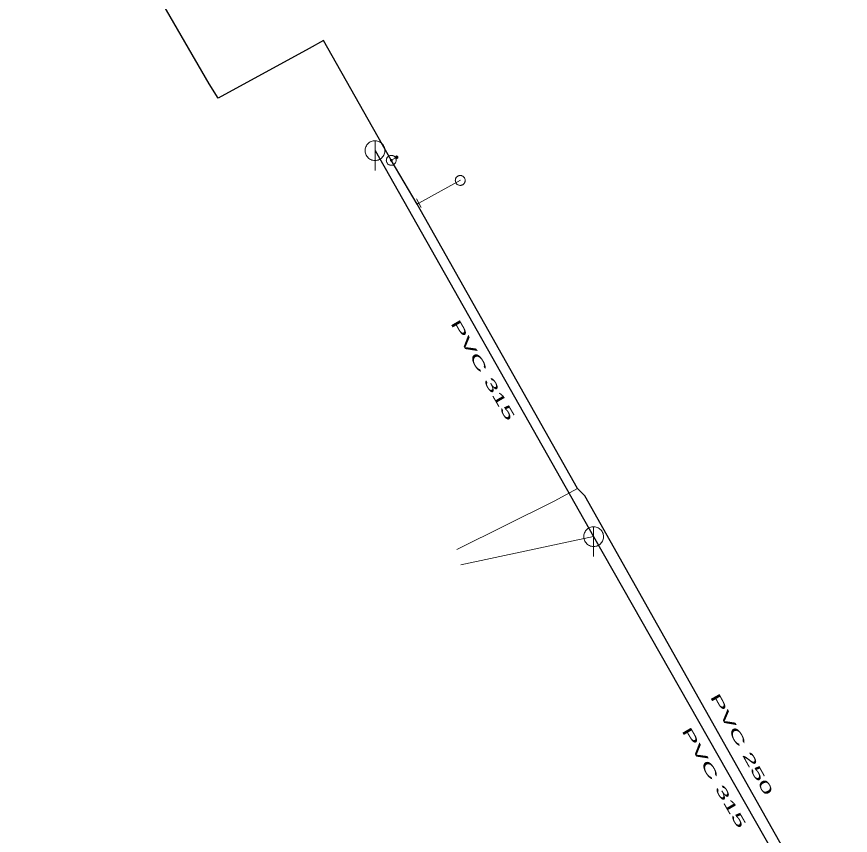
# Model space of a CAD drawing. Extents: x -807203 to -805207, y -993656 to -992505.
# Drawn here: x -806782.7 to -806698.5, y -992964 to -992881.3 of the extents above; entities that cross this region are included whole.
import ezdxf

# ---------------------------------------------------------------- set-up
doc = ezdxf.new("R2010")
doc.units = 0
doc.header["$LTSCALE"] = 0.4
for name, color, linetype, lineweight in [('1', 7, 'Continuous', 13), ('11', 7, 'Continuous', 13), ('13', 7, 'Continuous', 13), ('14', 7, 'Continuous', 25), ('17', 7, 'Continuous', 25), ('22', 7, 'Continuous', 13), ('23', 7, 'Continuous', 13), ('34', 7, 'Continuous', 13), ('47', 7, 'Continuous', 13), ('9', 7, 'Continuous', 13)]:
    doc.layers.add(name, color=color, linetype=linetype, lineweight=lineweight)

msp = doc.modelspace()

# ---------------------------------------------------------------- linework, layer by layer
at = {"layer": '11'}
msp.add_line((-806737.84, -992936.689), (-806724.449, -992933.829), dxfattribs=at)
at = {"layer": '13'}
msp.add_line((-806742.088, -992900.162), (-806737.898, -992897.848), dxfattribs=at)
msp.add_lwpolyline([(-806726.08, -992928.98), (-806728.42, -992930.24), (-806738.26, -992935.13)], dxfattribs=at)
at = {"layer": '14'}
for p, q in [((-806746.51, -992894.87), (-806724.449, -992933.829)), ((-806724.449, -992933.829), (-806699.85, -992977.12))]:
    msp.add_line(p, q, dxfattribs=at)
at = {"layer": '14', "lineweight": 13}
for p, q in [((-806744.869, -992895.849), (-806744.323, -992895.536)), ((-806742.088, -992900.162), (-806742.265, -992900.26))]:
    msp.add_line(p, q, dxfattribs=at)
at = {"layer": '17'}
for points in [[(-806744.869, -992895.849), (-806751.715, -992883.767), (-806753.16, -992884.579), (-806762.344, -992889.559), (-806763.23, -992888.129), (-806769.25, -992877.71), (-806781.199, -992856.899), (-806796.3, -992830.96), (-806805.559, -992815.579), (-806823.289, -992784.289), (-806834.87, -992763.203)], [(-806698.548, -992977.42), (-806698.73, -992976.969), (-806725.329, -992929.699), (-806726.079, -992928.98), (-806742.265, -992900.26), (-806744.869, -992895.849)]]:
    msp.add_lwpolyline(points, dxfattribs=at)
at = {"layer": '22'}
for p, q in [((-806746.51, -992896.87), (-806746.509, -992893.87)), ((-806724.449, -992935.829), (-806724.448, -992932.829))]:
    msp.add_line(p, q, dxfattribs=at)
for points in [[(-806745.51, -992894.87), (-806745.515, -992894.761), (-806745.533, -992894.653), (-806745.563, -992894.547), (-806745.603, -992894.446), (-806745.655, -992894.349), (-806745.717, -992894.259), (-806745.789, -992894.176), (-806745.869, -992894.102), (-806745.957, -992894.036), (-806746.051, -992893.981), (-806746.151, -992893.936), (-806746.256, -992893.903), (-806746.363, -992893.881), (-806746.472, -992893.871), (-806746.582, -992893.873), (-806746.69, -992893.887), (-806746.797, -992893.912), (-806746.9, -992893.949), (-806746.998, -992893.998), (-806747.09, -992894.056), (-806747.176, -992894.125), (-806747.253, -992894.202), (-806747.322, -992894.288), (-806747.381, -992894.38), (-806747.429, -992894.478), (-806747.466, -992894.581), (-806747.492, -992894.688), (-806747.506, -992894.796), (-806747.509, -992894.906), (-806747.499, -992895.015), (-806747.478, -992895.122), (-806747.444, -992895.226), (-806747.4, -992895.326), (-806747.345, -992895.421), (-806747.279, -992895.509), (-806747.205, -992895.589), (-806747.122, -992895.661), (-806747.032, -992895.723), (-806746.936, -992895.775), (-806746.834, -992895.816), (-806746.729, -992895.846), (-806746.621, -992895.864), (-806746.511, -992895.87), (-806746.402, -992895.864), (-806746.294, -992895.846), (-806746.189, -992895.817), (-806746.087, -992895.776), (-806745.99, -992895.724), (-806745.9, -992895.662), (-806745.817, -992895.591), (-806745.742, -992895.511), (-806745.677, -992895.423), (-806745.621, -992895.329), (-806745.577, -992895.229), (-806745.543, -992895.125), (-806745.521, -992895.017), (-806745.511, -992894.908)], [(-806723.449, -992933.829), (-806723.454, -992933.72), (-806723.472, -992933.612), (-806723.502, -992933.506), (-806723.542, -992933.405), (-806723.594, -992933.308), (-806723.656, -992933.218), (-806723.728, -992933.135), (-806723.808, -992933.061), (-806723.896, -992932.995), (-806723.99, -992932.94), (-806724.09, -992932.895), (-806724.195, -992932.862), (-806724.302, -992932.84), (-806724.411, -992932.83), (-806724.521, -992932.832), (-806724.629, -992932.846), (-806724.736, -992932.871), (-806724.839, -992932.908), (-806724.937, -992932.957), (-806725.029, -992933.015), (-806725.115, -992933.084), (-806725.192, -992933.161), (-806725.261, -992933.247), (-806725.32, -992933.339), (-806725.368, -992933.437), (-806725.405, -992933.54), (-806725.431, -992933.647), (-806725.445, -992933.755), (-806725.448, -992933.865), (-806725.438, -992933.974), (-806725.417, -992934.081), (-806725.383, -992934.185), (-806725.339, -992934.285), (-806725.284, -992934.38), (-806725.218, -992934.468), (-806725.144, -992934.548), (-806725.061, -992934.62), (-806724.971, -992934.682), (-806724.875, -992934.734), (-806724.773, -992934.775), (-806724.668, -992934.805), (-806724.56, -992934.823), (-806724.45, -992934.829), (-806724.341, -992934.823), (-806724.233, -992934.805), (-806724.128, -992934.776), (-806724.026, -992934.735), (-806723.929, -992934.683), (-806723.839, -992934.621), (-806723.756, -992934.55), (-806723.681, -992934.47), (-806723.616, -992934.382), (-806723.56, -992934.288), (-806723.516, -992934.188), (-806723.482, -992934.084), (-806723.46, -992933.976), (-806723.45, -992933.867)]]:
    msp.add_lwpolyline(points, close=True, dxfattribs=at)
at = {"layer": '23'}
for points in [[(-806737.471, -992897.632), (-806737.5, -992897.587), (-806737.533, -992897.546), (-806737.57, -992897.51), (-806737.61, -992897.477), (-806737.653, -992897.448), (-806737.701, -992897.424), (-806737.749, -992897.405), (-806737.799, -992897.391), (-806737.851, -992897.382), (-806737.903, -992897.379), (-806737.955, -992897.381), (-806738.008, -992897.389), (-806738.058, -992897.402), (-806738.106, -992897.421), (-806738.153, -992897.443), (-806738.198, -992897.473), (-806738.238, -992897.504), (-806738.276, -992897.542), (-806738.309, -992897.581), (-806738.338, -992897.624), (-806738.362, -992897.673), (-806738.381, -992897.721), (-806738.395, -992897.772), (-806738.404, -992897.823), (-806738.407, -992897.875), (-806738.404, -992897.928), (-806738.396, -992897.978), (-806738.383, -992898.029), (-806738.364, -992898.078), (-806738.342, -992898.125), (-806738.314, -992898.169), (-806738.281, -992898.211), (-806738.244, -992898.248), (-806738.204, -992898.281), (-806738.16, -992898.309), (-806738.114, -992898.333), (-806738.065, -992898.353), (-806738.014, -992898.367), (-806737.962, -992898.375)], [(-806738.276, -992897.542), (-806738.309, -992897.581), (-806738.338, -992897.624), (-806738.362, -992897.673), (-806738.381, -992897.721), (-806738.395, -992897.772), (-806738.404, -992897.823), (-806738.407, -992897.875), (-806738.404, -992897.928), (-806738.396, -992897.978), (-806738.383, -992898.029), (-806738.364, -992898.078), (-806738.342, -992898.125), (-806738.314, -992898.169), (-806738.281, -992898.211), (-806738.244, -992898.248), (-806738.204, -992898.281), (-806738.16, -992898.309), (-806738.114, -992898.333), (-806738.065, -992898.353), (-806738.014, -992898.367), (-806737.962, -992898.375), (-806737.911, -992898.379), (-806737.858, -992898.376), (-806737.807, -992898.369), (-806737.756, -992898.355), (-806737.708, -992898.336), (-806737.661, -992898.314), (-806737.617, -992898.285), (-806737.575, -992898.253), (-806737.538, -992898.216), (-806737.505, -992898.175), (-806737.476, -992898.131), (-806737.452, -992898.086), (-806737.433, -992898.036), (-806737.418, -992897.987), (-806737.41, -992897.935), (-806737.407, -992897.882), (-806737.409, -992897.83), (-806737.417, -992897.778)], [(-806737.962, -992898.375), (-806737.911, -992898.379), (-806737.858, -992898.376), (-806737.807, -992898.369), (-806737.756, -992898.355), (-806737.708, -992898.336), (-806737.661, -992898.314), (-806737.617, -992898.285), (-806737.575, -992898.253), (-806737.538, -992898.216), (-806737.505, -992898.175), (-806737.476, -992898.131), (-806737.452, -992898.086), (-806737.433, -992898.036), (-806737.418, -992897.987), (-806737.41, -992897.935), (-806737.407, -992897.882), (-806737.409, -992897.83), (-806737.417, -992897.778), (-806737.431, -992897.728), (-806737.449, -992897.679), (-806737.471, -992897.632), (-806737.5, -992897.587), (-806737.533, -992897.546), (-806737.57, -992897.51), (-806737.61, -992897.477), (-806737.653, -992897.448), (-806737.701, -992897.424), (-806737.749, -992897.405), (-806737.799, -992897.391), (-806737.851, -992897.382), (-806737.903, -992897.379), (-806737.955, -992897.381), (-806738.008, -992897.389), (-806738.058, -992897.402), (-806738.106, -992897.421), (-806738.153, -992897.443), (-806738.198, -992897.473), (-806738.238, -992897.504), (-806738.276, -992897.542)], [(-806737.417, -992897.778), (-806737.431, -992897.728), (-806737.449, -992897.679), (-806737.471, -992897.632)]]:
    msp.add_lwpolyline(points, dxfattribs=at)
at = {"layer": '34'}
msp.add_line((-806742.33, -992899.724), (-806741.846, -992900.599), dxfattribs=at)
at = {"layer": '47'}
for points in [[(-806744.614, -992896.279), (-806744.571, -992896.25), (-806744.53, -992896.217), (-806744.494, -992896.179), (-806744.461, -992896.139), (-806744.433, -992896.094), (-806744.41, -992896.047), (-806744.392, -992895.998), (-806744.379, -992895.947), (-806744.371, -992895.896), (-806744.369, -992895.844), (-806744.372, -992895.791), (-806744.381, -992895.74), (-806744.395, -992895.689), (-806744.414, -992895.641), (-806744.438, -992895.594), (-806744.467, -992895.551), (-806744.5, -992895.51), (-806744.538, -992895.473), (-806744.578, -992895.441), (-806744.623, -992895.413), (-806744.67, -992895.39), (-806744.719, -992895.371), (-806744.77, -992895.358), (-806744.821, -992895.35), (-806744.873, -992895.349), (-806744.926, -992895.352), (-806744.978, -992895.36), (-806745.028, -992895.375), (-806745.076, -992895.394), (-806745.123, -992895.418), (-806745.166, -992895.447), (-806745.207, -992895.48), (-806745.244, -992895.517), (-806745.276, -992895.558), (-806745.304, -992895.603), (-806745.328, -992895.649), (-806745.346, -992895.699), (-806745.359, -992895.749), (-806745.367, -992895.801), (-806745.368, -992895.853), (-806745.365, -992895.906), (-806745.357, -992895.957), (-806745.342, -992896.008), (-806745.323, -992896.056), (-806745.299, -992896.103), (-806745.27, -992896.146), (-806745.237, -992896.187), (-806745.2, -992896.223), (-806745.159, -992896.256), (-806745.114, -992896.284), (-806745.068, -992896.308), (-806745.019, -992896.325), (-806744.968, -992896.338), (-806744.916, -992896.346), (-806744.864, -992896.348), (-806744.811, -992896.345), (-806744.76, -992896.336), (-806744.709, -992896.322), (-806744.661, -992896.303)], [(-806744.827, -992895.919), (-806744.819, -992895.915), (-806744.813, -992895.909), (-806744.807, -992895.903), (-806744.802, -992895.896), (-806744.797, -992895.889), (-806744.794, -992895.881), (-806744.79, -992895.873), (-806744.788, -992895.865), (-806744.787, -992895.856), (-806744.787, -992895.848), (-806744.787, -992895.839), (-806744.789, -992895.83), (-806744.791, -992895.822), (-806744.793, -992895.815), (-806744.798, -992895.807), (-806744.802, -992895.799), (-806744.808, -992895.793), (-806744.814, -992895.787), (-806744.821, -992895.782), (-806744.828, -992895.777), (-806744.836, -992895.774), (-806744.844, -992895.77), (-806744.852, -992895.768), (-806744.861, -992895.766), (-806744.869, -992895.767), (-806744.878, -992895.767), (-806744.887, -992895.769), (-806744.895, -992895.771), (-806744.902, -992895.773), (-806744.91, -992895.778), (-806744.918, -992895.782), (-806744.924, -992895.788), (-806744.93, -992895.794), (-806744.935, -992895.801), (-806744.94, -992895.808), (-806744.944, -992895.815), (-806744.947, -992895.824), (-806744.949, -992895.832), (-806744.951, -992895.841), (-806744.95, -992895.849), (-806744.95, -992895.858), (-806744.948, -992895.867), (-806744.946, -992895.875), (-806744.944, -992895.882), (-806744.939, -992895.89), (-806744.935, -992895.898), (-806744.929, -992895.904), (-806744.923, -992895.91), (-806744.916, -992895.915), (-806744.909, -992895.92), (-806744.902, -992895.924), (-806744.893, -992895.927), (-806744.885, -992895.929), (-806744.876, -992895.93), (-806744.868, -992895.93), (-806744.859, -992895.93), (-806744.85, -992895.928), (-806744.842, -992895.926), (-806744.835, -992895.924)]]:
    msp.add_lwpolyline(points, close=True, dxfattribs=at)
at = {"layer": '9'}
for points in [[(-806744.449, -992895.536), (-806744.449, -992895.549), (-806744.446, -992895.562), (-806744.444, -992895.575), (-806744.439, -992895.587), (-806744.433, -992895.599), (-806744.426, -992895.61), (-806744.418, -992895.62), (-806744.407, -992895.63), (-806744.397, -992895.638), (-806744.387, -992895.645), (-806744.375, -992895.651), (-806744.363, -992895.656), (-806744.35, -992895.659), (-806744.337, -992895.661), (-806744.324, -992895.663), (-806744.311, -992895.662), (-806744.298, -992895.66), (-806744.285, -992895.657), (-806744.272, -992895.652), (-806744.261, -992895.646), (-806744.25, -992895.639), (-806744.24, -992895.631), (-806744.23, -992895.621), (-806744.222, -992895.611), (-806744.215, -992895.6), (-806744.209, -992895.588), (-806744.204, -992895.576), (-806744.201, -992895.563), (-806744.199, -992895.55), (-806744.196, -992895.537), (-806744.198, -992895.524), (-806744.2, -992895.511), (-806744.203, -992895.498), (-806744.208, -992895.486), (-806744.213, -992895.474), (-806744.221, -992895.463), (-806744.228, -992895.453), (-806744.239, -992895.443), (-806744.249, -992895.435), (-806744.26, -992895.428), (-806744.272, -992895.422), (-806744.284, -992895.417), (-806744.297, -992895.414), (-806744.309, -992895.412), (-806744.323, -992895.411), (-806744.336, -992895.411), (-806744.348, -992895.413), (-806744.362, -992895.416), (-806744.374, -992895.421), (-806744.386, -992895.427), (-806744.397, -992895.434), (-806744.407, -992895.442), (-806744.417, -992895.452), (-806744.424, -992895.462), (-806744.432, -992895.473), (-806744.438, -992895.485), (-806744.443, -992895.497), (-806744.446, -992895.51), (-806744.448, -992895.523)], [(-806744.429, -992895.536), (-806744.429, -992895.547), (-806744.428, -992895.558), (-806744.424, -992895.569), (-806744.421, -992895.579), (-806744.416, -992895.589), (-806744.41, -992895.598), (-806744.402, -992895.607), (-806744.395, -992895.615), (-806744.386, -992895.622), (-806744.377, -992895.628), (-806744.367, -992895.633), (-806744.357, -992895.637), (-806744.346, -992895.64), (-806744.335, -992895.643), (-806744.324, -992895.643), (-806744.313, -992895.643), (-806744.302, -992895.641), (-806744.291, -992895.638), (-806744.281, -992895.634), (-806744.271, -992895.629), (-806744.262, -992895.623), (-806744.253, -992895.616), (-806744.245, -992895.608), (-806744.238, -992895.599), (-806744.232, -992895.59), (-806744.227, -992895.58), (-806744.223, -992895.57), (-806744.22, -992895.559), (-806744.218, -992895.548), (-806744.217, -992895.537), (-806744.217, -992895.526), (-806744.218, -992895.515), (-806744.222, -992895.504), (-806744.226, -992895.494), (-806744.231, -992895.484), (-806744.237, -992895.475), (-806744.244, -992895.466), (-806744.252, -992895.458), (-806744.261, -992895.451), (-806744.27, -992895.445), (-806744.28, -992895.44), (-806744.289, -992895.436), (-806744.301, -992895.433), (-806744.311, -992895.431), (-806744.323, -992895.431), (-806744.334, -992895.43), (-806744.345, -992895.432), (-806744.356, -992895.435), (-806744.365, -992895.439), (-806744.375, -992895.444), (-806744.385, -992895.45), (-806744.394, -992895.457), (-806744.402, -992895.465), (-806744.409, -992895.474), (-806744.414, -992895.483), (-806744.419, -992895.493), (-806744.424, -992895.503), (-806744.427, -992895.514), (-806744.429, -992895.525)], [(-806744.41, -992895.536), (-806744.41, -992895.545), (-806744.409, -992895.554), (-806744.406, -992895.563), (-806744.402, -992895.571), (-806744.399, -992895.579), (-806744.394, -992895.587), (-806744.387, -992895.594), (-806744.382, -992895.6), (-806744.375, -992895.606), (-806744.367, -992895.611), (-806744.358, -992895.615), (-806744.351, -992895.618), (-806744.342, -992895.621), (-806744.333, -992895.622), (-806744.324, -992895.624), (-806744.315, -992895.623), (-806744.306, -992895.622), (-806744.297, -992895.619), (-806744.289, -992895.616), (-806744.281, -992895.612), (-806744.272, -992895.607), (-806744.266, -992895.601), (-806744.26, -992895.595), (-806744.254, -992895.588), (-806744.249, -992895.58), (-806744.245, -992895.572), (-806744.242, -992895.564), (-806744.239, -992895.555), (-806744.238, -992895.546), (-806744.235, -992895.537), (-806744.237, -992895.528), (-806744.238, -992895.519), (-806744.24, -992895.51), (-806744.244, -992895.502), (-806744.248, -992895.494), (-806744.253, -992895.486), (-806744.259, -992895.479), (-806744.265, -992895.473), (-806744.272, -992895.467), (-806744.28, -992895.462), (-806744.288, -992895.458), (-806744.296, -992895.455), (-806744.304, -992895.452), (-806744.314, -992895.451), (-806744.323, -992895.45), (-806744.331, -992895.45), (-806744.341, -992895.451), (-806744.35, -992895.454), (-806744.358, -992895.457), (-806744.365, -992895.461), (-806744.374, -992895.466), (-806744.38, -992895.472), (-806744.387, -992895.478), (-806744.392, -992895.485), (-806744.397, -992895.493), (-806744.402, -992895.501), (-806744.405, -992895.509), (-806744.407, -992895.518), (-806744.409, -992895.527)], [(-806744.39, -992895.536), (-806744.39, -992895.543), (-806744.389, -992895.55), (-806744.387, -992895.557), (-806744.385, -992895.563), (-806744.382, -992895.569), (-806744.378, -992895.575), (-806744.374, -992895.581), (-806744.369, -992895.586), (-806744.363, -992895.59), (-806744.357, -992895.594), (-806744.351, -992895.597), (-806744.345, -992895.6), (-806744.338, -992895.601), (-806744.331, -992895.604), (-806744.324, -992895.604), (-806744.316, -992895.604), (-806744.309, -992895.602), (-806744.303, -992895.601), (-806744.297, -992895.598), (-806744.289, -992895.595), (-806744.285, -992895.591), (-806744.279, -992895.587), (-806744.274, -992895.582), (-806744.27, -992895.576), (-806744.266, -992895.57), (-806744.262, -992895.564), (-806744.26, -992895.558), (-806744.258, -992895.551), (-806744.257, -992895.544), (-806744.255, -992895.537), (-806744.255, -992895.53), (-806744.257, -992895.523), (-806744.259, -992895.516), (-806744.262, -992895.51), (-806744.265, -992895.503), (-806744.269, -992895.498), (-806744.272, -992895.492), (-806744.277, -992895.487), (-806744.284, -992895.483), (-806744.289, -992895.479), (-806744.296, -992895.476), (-806744.302, -992895.473), (-806744.309, -992895.471), (-806744.316, -992895.47), (-806744.323, -992895.47), (-806744.33, -992895.47), (-806744.337, -992895.47), (-806744.343, -992895.472), (-806744.35, -992895.475), (-806744.356, -992895.478), (-806744.362, -992895.482), (-806744.368, -992895.486), (-806744.373, -992895.491), (-806744.377, -992895.497), (-806744.38, -992895.502), (-806744.384, -992895.509), (-806744.387, -992895.515), (-806744.387, -992895.522), (-806744.39, -992895.529)], [(-806744.37, -992895.536), (-806744.37, -992895.541), (-806744.37, -992895.546), (-806744.369, -992895.551), (-806744.367, -992895.555), (-806744.365, -992895.56), (-806744.362, -992895.564), (-806744.358, -992895.567), (-806744.355, -992895.571), (-806744.352, -992895.574), (-806744.348, -992895.577), (-806744.343, -992895.579), (-806744.338, -992895.581), (-806744.334, -992895.582), (-806744.329, -992895.584), (-806744.324, -992895.584), (-806744.319, -992895.584), (-806744.314, -992895.583), (-806744.309, -992895.582), (-806744.304, -992895.58), (-806744.299, -992895.578), (-806744.296, -992895.575), (-806744.292, -992895.572), (-806744.289, -992895.568), (-806744.286, -992895.565), (-806744.282, -992895.561), (-806744.281, -992895.556), (-806744.279, -992895.552), (-806744.277, -992895.547), (-806744.277, -992895.542), (-806744.276, -992895.537), (-806744.276, -992895.532), (-806744.277, -992895.527), (-806744.277, -992895.522), (-806744.28, -992895.518), (-806744.282, -992895.513), (-806744.285, -992895.509), (-806744.288, -992895.505), (-806744.291, -992895.502), (-806744.294, -992895.499), (-806744.299, -992895.496), (-806744.304, -992895.494), (-806744.308, -992895.492), (-806744.313, -992895.491), (-806744.318, -992895.49), (-806744.323, -992895.49), (-806744.328, -992895.49), (-806744.333, -992895.491), (-806744.338, -992895.491), (-806744.342, -992895.493), (-806744.347, -992895.495), (-806744.351, -992895.498), (-806744.353, -992895.501), (-806744.358, -992895.504), (-806744.36, -992895.508), (-806744.364, -992895.512), (-806744.365, -992895.517), (-806744.368, -992895.521), (-806744.369, -992895.526), (-806744.37, -992895.531)], [(-806744.35, -992895.536), (-806744.35, -992895.539), (-806744.351, -992895.542), (-806744.35, -992895.544), (-806744.348, -992895.547), (-806744.348, -992895.55), (-806744.346, -992895.552), (-806744.343, -992895.554), (-806744.342, -992895.556), (-806744.34, -992895.558), (-806744.338, -992895.56), (-806744.335, -992895.562), (-806744.331, -992895.563), (-806744.33, -992895.563), (-806744.326, -992895.564), (-806744.324, -992895.564), (-806744.321, -992895.564), (-806744.318, -992895.564), (-806744.315, -992895.563), (-806744.313, -992895.562), (-806744.309, -992895.561), (-806744.308, -992895.559), (-806744.304, -992895.557), (-806744.303, -992895.555), (-806744.302, -992895.553), (-806744.299, -992895.551), (-806744.299, -992895.548), (-806744.297, -992895.545), (-806744.297, -992895.543), (-806744.296, -992895.54), (-806744.294, -992895.537), (-806744.296, -992895.534), (-806744.296, -992895.531), (-806744.297, -992895.528), (-806744.298, -992895.526), (-806744.299, -992895.523), (-806744.301, -992895.521), (-806744.302, -992895.518), (-806744.304, -992895.516), (-806744.307, -992895.515), (-806744.309, -992895.513), (-806744.311, -992895.512), (-806744.314, -992895.511), (-806744.316, -992895.51), (-806744.32, -992895.51), (-806744.323, -992895.509), (-806744.326, -992895.51), (-806744.329, -992895.509), (-806744.331, -992895.511), (-806744.334, -992895.511), (-806744.337, -992895.512), (-806744.338, -992895.514), (-806744.341, -992895.515), (-806744.343, -992895.517), (-806744.345, -992895.52), (-806744.347, -992895.522), (-806744.348, -992895.525), (-806744.348, -992895.527), (-806744.35, -992895.53), (-806744.35, -992895.533)], [(-806744.331, -992895.536), (-806744.331, -992895.538), (-806744.331, -992895.538), (-806744.33, -992895.538), (-806744.33, -992895.54), (-806744.331, -992895.541), (-806744.329, -992895.541), (-806744.329, -992895.541), (-806744.329, -992895.543), (-806744.329, -992895.543), (-806744.328, -992895.544), (-806744.326, -992895.544), (-806744.326, -992895.544), (-806744.326, -992895.545), (-806744.324, -992895.545), (-806744.324, -992895.545), (-806744.323, -992895.545), (-806744.321, -992895.545), (-806744.321, -992895.544), (-806744.321, -992895.544), (-806744.319, -992895.544), (-806744.319, -992895.543), (-806744.319, -992895.543), (-806744.318, -992895.542), (-806744.318, -992895.542), (-806744.316, -992895.541), (-806744.316, -992895.54), (-806744.315, -992895.539), (-806744.315, -992895.539), (-806744.315, -992895.538), (-806744.315, -992895.537), (-806744.315, -992895.536), (-806744.315, -992895.535), (-806744.315, -992895.535), (-806744.316, -992895.534), (-806744.316, -992895.533), (-806744.316, -992895.532), (-806744.316, -992895.532), (-806744.318, -992895.531), (-806744.318, -992895.531), (-806744.319, -992895.53), (-806744.32, -992895.53), (-806744.321, -992895.529), (-806744.321, -992895.529), (-806744.321, -992895.529), (-806744.323, -992895.529), (-806744.324, -992895.529), (-806744.325, -992895.529), (-806744.325, -992895.529), (-806744.326, -992895.53), (-806744.326, -992895.529), (-806744.328, -992895.531), (-806744.328, -992895.531), (-806744.329, -992895.531), (-806744.329, -992895.531), (-806744.33, -992895.533), (-806744.33, -992895.534), (-806744.33, -992895.535), (-806744.331, -992895.535), (-806744.331, -992895.536)]]:
    msp.add_lwpolyline(points, close=True, dxfattribs=at)

# ---------------------------------------------------------------- texts
at = {"layer": '1', "width": 2.15}
for s, rotation, p in [('PVC 315 ', 300, (-806738.931, -992912.281)), ('PVC 250 ', 299, (-806712.737, -992949.994)), ('PVC 315 ', 300, (-806715.604, -992953.412))]:
    msp.add_text(s, height=1, rotation=rotation, dxfattribs=at).set_placement(p)

doc.saveas('drawing.dxf')
